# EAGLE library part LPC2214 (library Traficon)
16/32-bit ARM microcontrollers; 256 kB ISP/IAP Flash, 16kB RAM with 10-bit ADC and external memory interface
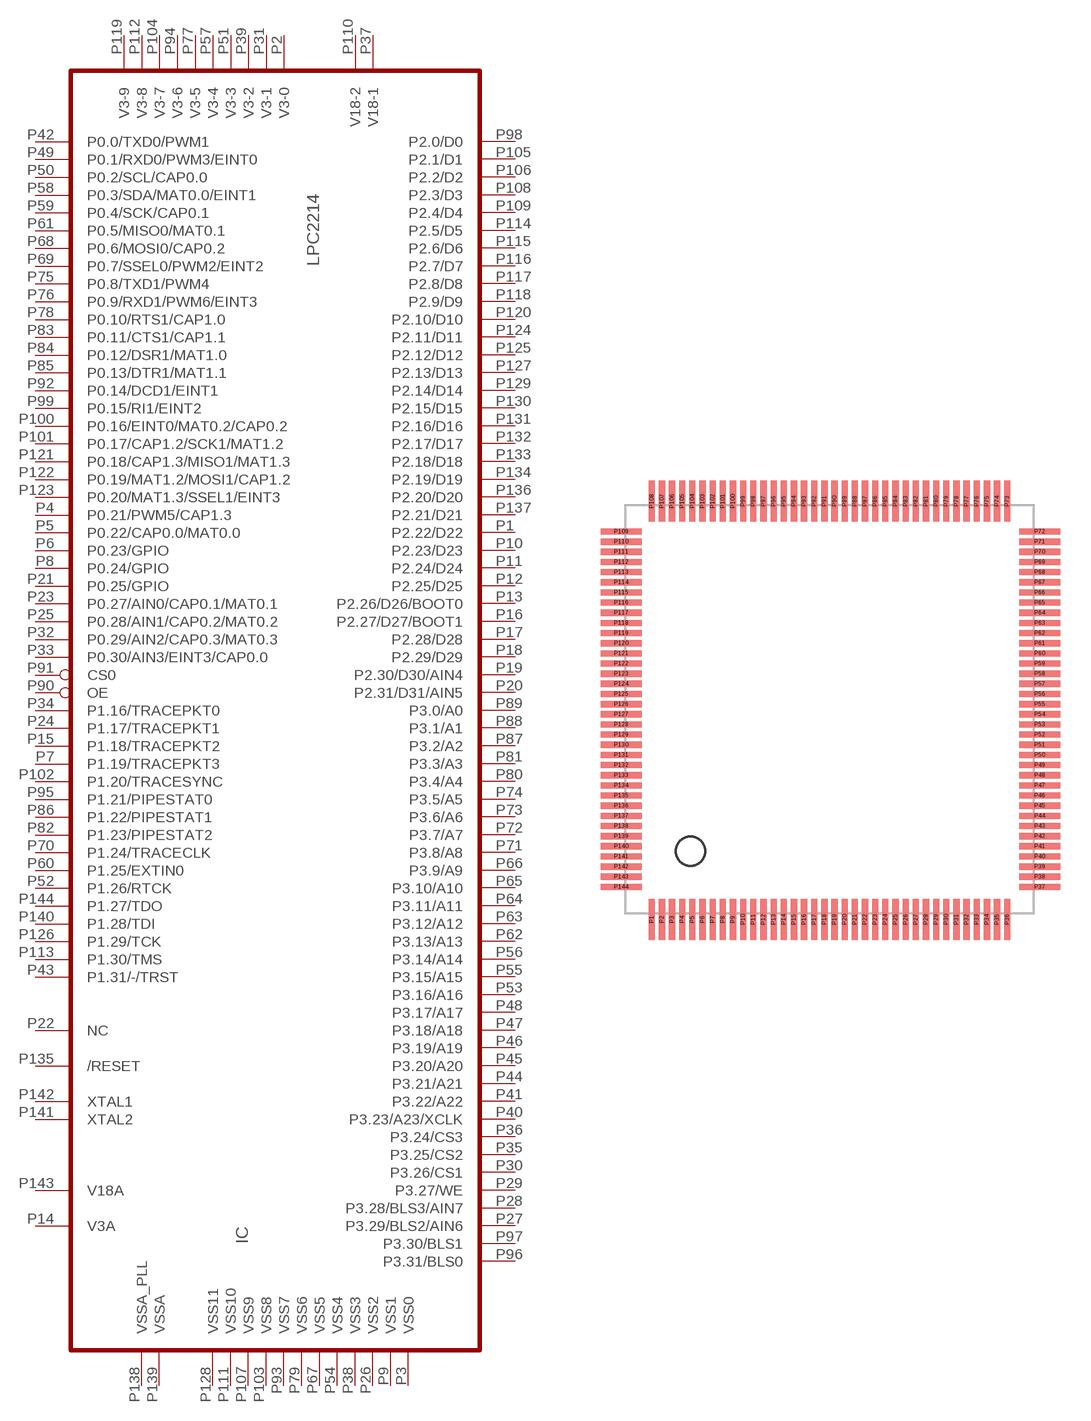
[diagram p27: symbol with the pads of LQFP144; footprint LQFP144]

Designator prefix IC

## LPC2214  [LQFP144]
P1  P2.22/D22
P2  V3-0  pas
P3  VSS0  pas
P4  P0.21/PWM5/CAP1.3
P5  P0.22/CAP0.0/MAT0.0
P6  P0.23/GPIO
P7  P1.19/TRACEPKT3
P8  P0.24/GPIO
P9  VSS1  pas
P10  P2.23/D23
P11  P2.24/D24
P12  P2.25/D25
P13  P2.26/D26/BOOT0
P14  V3A  pas
P15  P1.18/TRACEPKT2
P16  P2.27/D27/BOOT1
P17  P2.28/D28
P18  P2.29/D29
P19  P2.30/D30/AIN4
P20  P2.31/D31/AIN5
P21  P0.25/GPIO
P22  NC  nc
P23  P0.27/AIN0/CAP0.1/MAT0.1
P24  P1.17/TRACEPKT1
P25  P0.28/AIN1/CAP0.2/MAT0.2
P26  VSS2  pas
P27  P3.29/BLS2/AIN6
P28  P3.28/BLS3/AIN7
P29  P3.27/WE
P30  P3.26/CS1
P31  V3-1  pas
P32  P0.29/AIN2/CAP0.3/MAT0.3
P33  P0.30/AIN3/EINT3/CAP0.0
P34  P1.16/TRACEPKT0
P35  P3.25/CS2
P36  P3.24/CS3
P37  V18-1  pas
P38  VSS3  pas
P39  V3-2  pas
P40  P3.23/A23/XCLK
P41  P3.22/A22
P42  P0.0/TXD0/PWM1
P43  P1.31/-/TRST
P44  P3.21/A21
P45  P3.20/A20
P46  P3.19/A19
P47  P3.18/A18
P48  P3.17/A17
P49  P0.1/RXD0/PWM3/EINT0
P50  P0.2/SCL/CAP0.0
P51  V3-3  pas
P52  P1.26/RTCK
P53  P3.16/A16
P54  VSS4  pas
P55  P3.15/A15
P56  P3.14/A14
P57  V3-4  pas
P58  P0.3/SDA/MAT0.0/EINT1
P59  P0.4/SCK/CAP0.1
P60  P1.25/EXTIN0
P61  P0.5/MISO0/MAT0.1
P62  P3.13/A13
P63  P3.12/A12
P64  P3.11/A11
P65  P3.10/A10
P66  P3.9/A9
P67  VSS5  pas
P68  P0.6/MOSI0/CAP0.2
P69  P0.7/SSEL0/PWM2/EINT2
P70  P1.24/TRACECLK
P71  P3.8/A8
P72  P3.7/A7
P73  P3.6/A6
P74  P3.5/A5
P75  P0.8/TXD1/PWM4
P76  P0.9/RXD1/PWM6/EINT3
P77  V3-5  pas
P78  P0.10/RTS1/CAP1.0
P79  VSS6  pas
P80  P3.4/A4
P81  P3.3/A3
P82  P1.23/PIPESTAT2
P83  P0.11/CTS1/CAP1.1
P84  P0.12/DSR1/MAT1.0
P85  P0.13/DTR1/MAT1.1
P86  P1.22/PIPESTAT1
P87  P3.2/A2
P88  P3.1/A1
P89  P3.0/A0
P90  OE  in
P91  CS0  in
P92  P0.14/DCD1/EINT1
P93  VSS7  pas
P94  V3-6  pas
P95  P1.21/PIPESTAT0
P96  P3.31/BLS0
P97  P3.30/BLS1
P98  P2.0/D0
P99  P0.15/RI1/EINT2
P100  P0.16/EINT0/MAT0.2/CAP0.2
P101  P0.17/CAP1.2/SCK1/MAT1.2
P102  P1.20/TRACESYNC
P103  VSS8  pas
P104  V3-7  pas
P105  P2.1/D1
P106  P2.2/D2
P107  VSS9  pas
P108  P2.3/D3
P109  P2.4/D4
P110  V18-2  pas
P111  VSS10  pas
P112  V3-8  pas
P113  P1.30/TMS
P114  P2.5/D5
P115  P2.6/D6
P116  P2.7/D7
P117  P2.8/D8
P118  P2.9/D9
P119  V3-9  pas
P120  P2.10/D10
P121  P0.18/CAP1.3/MISO1/MAT1.3
P122  P0.19/MAT1.2/MOSI1/CAP1.2
P123  P0.20/MAT1.3/SSEL1/EINT3
P124  P2.11/D11
P125  P2.12/D12
P126  P1.29/TCK
P127  P2.13/D13
P128  VSS11  pas
P129  P2.14/D14
P130  P2.15/D15
P131  P2.16/D16
P132  P2.17/D17
P133  P2.18/D18
P134  P2.19/D19
P135  /RESET  in
P136  P2.20/D20
P137  P2.21/D21
P138  VSSA_PLL  pas
P139  VSSA  pas
P140  P1.28/TDI
P141  XTAL2  out
P142  XTAL1  in
P143  V18A  pas
P144  P1.27/TDO

## Footprint LQFP144 (pad centres in mm)
smd 0.305 x 2: P1 -8.89,-10.34; P2 -8.39,-10.34; P3 -7.89,-10.34; P4 -7.39,-10.34; P5 -6.89,-10.34; P6 -6.39,-10.34; P7 -5.89,-10.34; P8 -5.39,-10.34; P9 -4.89,-10.34; P10 -4.39,-10.34; P11 -3.89,-10.34; P12 -3.39,-10.34; P13 -2.89,-10.34; P14 -2.39,-10.34; P15 -1.89,-10.34; P16 -1.39,-10.34; P17 -0.89,-10.34; P18 -0.39,-10.34; P19 0.11,-10.34; P20 0.61,-10.34; P21 1.11,-10.34; P22 1.61,-10.34; P23 2.11,-10.34; P24 2.61,-10.34; P25 3.11,-10.34; P26 3.61,-10.34; P27 4.11,-10.34; P28 4.61,-10.34; P29 5.11,-10.34; P30 5.61,-10.34; P31 6.11,-10.34; P32 6.61,-10.34; P33 7.11,-10.34; P34 7.61,-10.34; P35 8.11,-10.34; P36 8.61,-10.34; P73 8.61,10.26; P74 8.11,10.26; P75 7.61,10.26; P76 7.11,10.26; P77 6.61,10.26; P78 6.11,10.26; P79 5.61,10.26; P80 5.11,10.26; P81 4.61,10.26; P82 4.11,10.26; P83 3.61,10.26; P84 3.11,10.26; P85 2.61,10.26; P86 2.11,10.26; P87 1.61,10.26; P88 1.11,10.26; P89 0.61,10.26; P90 0.11,10.26; P91 -0.39,10.26; P92 -0.89,10.26; P93 -1.39,10.26; P94 -1.89,10.26; P95 -2.39,10.26; P96 -2.89,10.26; P97 -3.39,10.26; P98 -3.89,10.26; P99 -4.39,10.26; P100 -4.89,10.26; P101 -5.39,10.26; P102 -5.89,10.26; P103 -6.39,10.26; P104 -6.89,10.26; P105 -7.39,10.26; P106 -7.89,10.26; P107 -8.39,10.26; P108 -8.89,10.26
smd 2 x 0.305: P37 10.21,-8.74; P38 10.21,-8.24; P39 10.21,-7.74; P40 10.21,-7.24; P41 10.21,-6.74; P42 10.21,-6.24; P43 10.21,-5.74; P44 10.21,-5.24; P45 10.21,-4.74; P46 10.21,-4.24; P47 10.21,-3.74; P48 10.21,-3.24; P49 10.21,-2.74; P50 10.21,-2.24; P51 10.21,-1.74; P52 10.21,-1.24; P53 10.21,-0.74; P54 10.21,-0.24; P55 10.21,0.26; P56 10.21,0.76; P57 10.21,1.26; P58 10.21,1.76; P59 10.21,2.26; P60 10.21,2.76; P61 10.21,3.26; P62 10.21,3.76; P63 10.21,4.26; P64 10.21,4.76; P65 10.21,5.26; P66 10.21,5.76; P67 10.21,6.26; P68 10.21,6.76; P69 10.21,7.26; P70 10.21,7.76; P71 10.21,8.26; P72 10.21,8.76; P109 -10.39,8.76; P110 -10.39,8.26; P111 -10.39,7.76; P112 -10.39,7.26; P113 -10.39,6.76; P114 -10.39,6.26; P115 -10.39,5.76; P116 -10.39,5.26; P117 -10.39,4.76; P118 -10.39,4.26; P119 -10.39,3.76; P120 -10.39,3.26; P121 -10.39,2.76; P122 -10.39,2.26; P123 -10.39,1.76; P124 -10.39,1.26; P125 -10.39,0.76; P126 -10.39,0.26; P127 -10.39,-0.24; P128 -10.39,-0.74; P129 -10.39,-1.24; P130 -10.39,-1.74; P131 -10.39,-2.24; P132 -10.39,-2.74; P133 -10.39,-3.24; P134 -10.39,-3.74; P135 -10.39,-4.24; P136 -10.39,-4.74; P137 -10.39,-5.24; P138 -10.39,-5.74; P139 -10.39,-6.24; P140 -10.39,-6.74; P141 -10.39,-7.24; P142 -10.39,-7.74; P143 -10.39,-8.24; P144 -10.39,-8.74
